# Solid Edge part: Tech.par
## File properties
Title: Tech 54,5x35,8 cm
Author: DESYS
Template: Normal.par
Last saved by: Luca
Revision: 6
Application: Solid Edge
Tipo di contenuto documento: 0
Precisione: 0.990
Document Number: 8037
Revision: 0
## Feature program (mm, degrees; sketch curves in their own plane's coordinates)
sketch for "unnamed Protrusion 1" plane through (0, 0, 0) normal (0, 0, 1) x-axis (1, 0, 0)
  line (-272.5, -179) -> (272.5, -179)
  line (272.5, -179) -> (272.5, 179)
  line (272.5, 179) -> (-272.5, 179)
  line (-272.5, 179) -> (-272.5, -179)
  dimension (linear) = 272.5
  dimension (linear) = 272.5
extrude "unnamed Protrusion 1" add finite 15 along -normal
sketch for "ExtrudedProtrusion_2" plane through (0, 0, -15) normal (0, 0, -1) x-axis (-1, 0, 0)
  line (-255, 179) -> (-255, -161)
  line (-255, -161) -> (255, -161)
  line (255, -161) -> (255, 179)
  dimension (linear) = 255
  dimension (linear) = 255
extrude "ExtrudedProtrusion_2" add finite 145 along +normal
sketch for "ExtrudedCutout_1" plane through (0, 0, 0) normal (0, 0, 1) x-axis (1, 0, 0)
  line (-247.5, -154) -> (247.5, -154)
  line (247.5, -154) -> (247.5, 169)
  line (247.5, 169) -> (-247.5, 169)
  line (-247.5, 169) -> (-247.5, -154)
  dimension (linear) = 247.5
  dimension (linear) = 247.5
extrude "ExtrudedCutout_1" cut finite 100 along -normal  Treatment1_DraftAngle = 20 deg
chamfer "Smusso_1" setback 30
sketch for "Foro_1" plane through (0, 7.5, -100) normal (0, 0, 1) x-axis (-1, 0, 0)
  hole centre (0, -0.002) bore radius 25
hole "Foro_1" diameter 50 through
sketch for "ExtrudedCutout_2" plane through (0, 9, -160) normal (0, 0, -1) x-axis (-1, 0, 0)
  line (-163.575, -135) -> (176.425, -135)
  arc centre (176.425, -95) radius 40 from (216.425, -95) to (176.425, -135) cw
  line (216.425, -95) -> (216.425, 85)
  arc centre (176.425, 85) radius 40 from (176.425, 125) to (216.425, 85) cw
  line (176.425, 125) -> (-163.575, 125)
  arc centre (-163.575, 85) radius 40 from (-163.575, 125) to (-203.575, 85) ccw
  line (-203.575, 85) -> (-203.575, -95)
  arc centre (-163.575, -95) radius 40 from (-203.575, -95) to (-163.575, -135) ccw
  dimension (linear) = 176.425
  dimension (linear) = 203.575
extrude "ExtrudedCutout_2" cut finite 30 along -normal
sketch for "ExtrudedCutout_3" plane through (0, 0, 0) normal (1, 0, 0) x-axis (0, 1, 0)
  line (-122.3609, -130) -> (-152.895, -97.2179)
  line (-152.895, -97.2179) -> (-161, -15)
  line (-179, -15) -> (-161, -15)
  line (-182.082, -193.7595) -> (-179, -15)
  line (-122.3609, -193.7595) -> (-182.082, -193.7595)
  line (-122.3609, -130) -> (-122.3609, -193.7595)
extrude "ExtrudedCutout_3" cut finite 270 symmetric
draft "Draft_2"  Angles1 = 23 deg
sketch for "ExtrudedProtrusion_3" plane through (-6.425, 0.36, -130) normal (0, 0, -1) x-axis (-1, 0, 0)
  circle centre (-6.425, 7.142) radius 35
extrude "ExtrudedProtrusion_3" add finite 30 along +normal
sketch for "ExtrudedProtrusion_4" plane through (0, 0, 0) normal (1, 0, 0) x-axis (0, 1, 0)
  line (-169.3718, -96.2869) -> (-179, -15)
  arc centre (-139.5801, -92.7581) radius 30 from (-169.3718, -96.2869) to (-158.9289, -115.6846) ccw
  line (-158.9289, -115.6846) -> (-125.2051, -144.1458)
  arc centre (-105.8563, -121.2194) radius 30 from (-125.2051, -144.1458) to (-105.8563, -151.2194) ccw
  line (-105.8563, -151.2194) -> (17.8184, -151.2194)
  line (17.8184, -151.2194) -> (17.8184, -130)
extrude "ExtrudedProtrusion_4" add finite 40 symmetric
sketch for "Foro_2" plane through (0, 7.502, -160) normal (0, 0, -1) x-axis (0, -1, 0)
  hole centre (0, 0) bore radius 25
hole "Foro_2" diameter 50 through
fillet "Rotondo_2" radius 10
fillet "Rotondo_3" radius 20
fillet "Rotondo_5" radius 5
fillet "Rotondo_6" radius 10
fillet "Rotondo_7" radius 5
fillet "Rotondo_8" radius 5
fillet "Rotondo_9" radius 5
fillet "Rotondo_10" radius 15
sketch for "Foro_3" plane through (0, 0, 0) normal (0, -1, 0) x-axis (1, 0, 0)
  hole centre (0, -40) bore radius 10
hole "Foro_3" diameter 20 finite
fillet "Rotondo_11" radius 5
fillet "Rotondo_12" radius 10
fillet "Rotondo_13" radius 5
draft "Draft_3"  Angles1 = 5 deg
fillet "Rotondo_15" radius 5
fillet "Rotondo_16" radius 10
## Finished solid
Body 1: solid body, 207 faces, 449 edges, 244 vertices.
  Faces by surface: cylinder 89, blend 44, plane 42, torus 15, sphere 12, cone 5
  Edges by curve: line 187, circle 155, ellipse 77, intersection 30
Bounding box of the edges (mm; curved faces can reach further): 545.000 x 358.000 x 160.000, from (-272.5, -179, -160) to (272.5, 179, 0).
Cylindrical faces by radius (mm): R5 x52, R10 x29, R20 x5, R25 x1, R30 x2
Conical faces (half-angle, radius in mm at the cone's reference point): 5 deg R35 x1, 23 deg R40 x4
Toroidal faces (ring radius, tube radius in mm): R14.028 r20 x4, R15 r5 x4, R30.4183 r5 x1, R40 r15 x1, R46.6189 r10 x4, R46.788 r10 x1
Spherical faces by radius (mm): R5 x8, R10 x4
Planar faces by outward normal: +x 2, +y 2, +z 2, -x 2, -y 3, -z 6, oblique 25
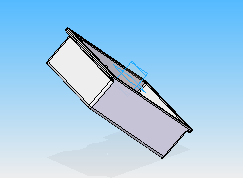
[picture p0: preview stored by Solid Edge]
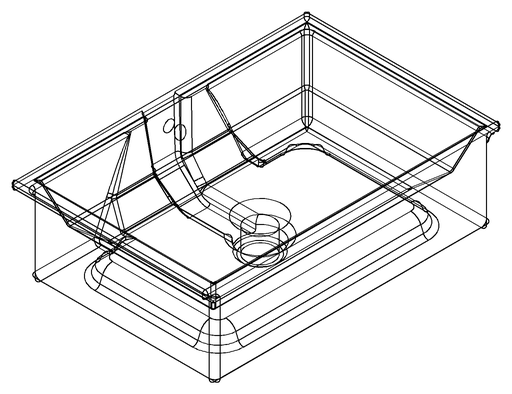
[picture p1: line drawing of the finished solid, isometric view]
